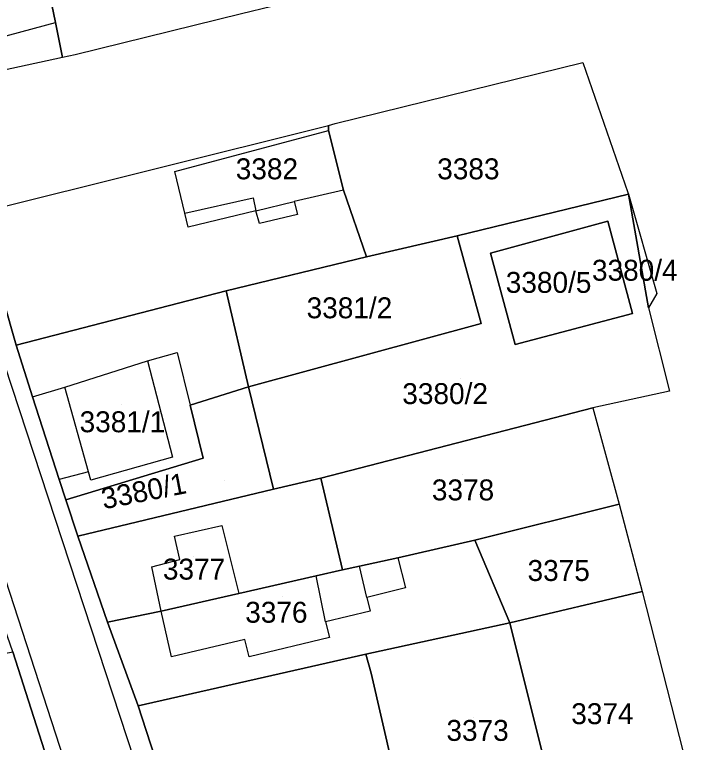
# Model space of a CAD drawing. Extents: x -262657 to -261595, y -1238015 to -1237156.
# Drawn here: x -261971.4 to -261907.1, y -1237612 to -1237542.4 of the extents above; entities that cross this region are included whole.
import ezdxf

# ---------------------------------------------------------------- set-up
doc = ezdxf.new("R2010")
doc.units = 0
for name, color, linetype in [('body_kn', 7, 'Continuous'), ('kladpar_druhypozemkov', 7, 'Continuous'), ('kladpar_hranice', 7, 'Continuous'), ('kladpar_parcelnecisla', 7, 'Continuous'), ('kladpar_plochy', 7, 'Continuous'), ('zappar_hrandruhpozemk', 7, 'Continuous')]:
    doc.layers.add(name, color=color, linetype=linetype)

msp = doc.modelspace()

# ---------------------------------------------------------------- linework, layer by layer
at = {"layer": 'body_kn'}
for p, q in [((-261967.44, -1237543.19), (-261967.44, -1237543.19)), ((-261966.77, -1237546.53), (-261966.77, -1237546.53)), ((-261965.58, -1237546.27), (-261965.58, -1237546.27)), ((-261917.09, -1237547.02), (-261917.09, -1237547.02)), ((-261941.38, -1237553.04), (-261941.38, -1237553.04)), ((-261940.74, -1237552.85), (-261940.74, -1237552.85)), ((-261941.37, -1237553.51), (-261941.37, -1237553.51)), ((-261956.05, -1237557.44), (-261956.05, -1237557.44)), ((-261939.95, -1237559.2), (-261939.95, -1237559.2)), ((-261939.95, -1237559.2), (-261939.95, -1237559.2)), ((-261912.79, -1237559.44), (-261912.79, -1237559.44)), ((-261912.73, -1237559.6), (-261912.73, -1237559.6)), ((-261912.73, -1237559.6), (-261912.73, -1237559.6)), ((-261948.58, -1237559.94), (-261948.58, -1237559.94)), ((-261944.65, -1237560.29), (-261944.65, -1237560.29)), ((-261955.09, -1237561.42), (-261955.09, -1237561.42)), ((-261955.09, -1237561.42), (-261955.09, -1237561.42)), ((-261948.33, -1237561.2), (-261948.33, -1237561.2)), ((-261948.33, -1237561.2), (-261948.33, -1237561.2)), ((-261944.35, -1237561.52), (-261944.35, -1237561.52)), ((-261947.97, -1237562.4), (-261947.97, -1237562.4)), ((-261914.68, -1237562.17), (-261914.68, -1237562.17)), ((-261914.68, -1237562.17), (-261914.68, -1237562.17)), ((-261954.79, -1237562.75), (-261954.79, -1237562.75)), ((-261929.09, -1237563.57), (-261929.09, -1237563.57)), ((-261925.89, -1237565.22), (-261925.89, -1237565.22)), ((-261937.76, -1237565.58), (-261937.76, -1237565.58)), ((-261937.76, -1237565.58), (-261937.76, -1237565.58)), ((-261951.16, -1237568.82), (-261951.16, -1237568.82)), ((-261951.16, -1237568.82), (-261951.16, -1237568.82)), ((-261910.02, -1237569.07), (-261910.02, -1237569.07)), ((-261910.8, -1237570.46), (-261910.8, -1237570.46)), ((-261912.35, -1237570.99), (-261912.35, -1237570.99)), ((-261926.78, -1237571.94), (-261926.78, -1237571.94)), ((-261971.2, -1237574.01), (-261971.2, -1237574.01)), ((-261923.56, -1237573.97), (-261923.56, -1237573.97)), ((-261955.83, -1237574.71), (-261955.83, -1237574.71)), ((-261958.65, -1237575.53), (-261958.65, -1237575.53)), ((-261958.65, -1237575.53), (-261958.65, -1237575.53)), ((-261966.56, -1237578.03), (-261966.56, -1237578.03)), ((-261949.03, -1237578.01), (-261949.03, -1237578.01)), ((-261949.03, -1237578.01), (-261949.03, -1237578.01)), ((-261908.81, -1237578.43), (-261908.81, -1237578.43)), ((-261908.81, -1237578.43), (-261908.81, -1237578.43)), ((-261969.66, -1237578.95), (-261969.66, -1237578.95)), ((-261969.66, -1237578.95), (-261969.66, -1237578.95)), ((-261954.59, -1237579.76), (-261954.59, -1237579.76)), ((-261916.14, -1237580.02), (-261916.14, -1237580.02)), ((-261916.14, -1237580.02), (-261916.14, -1237580.02)), ((-261956.27, -1237584.73), (-261956.27, -1237584.73)), ((-261953.35, -1237584.81), (-261953.35, -1237584.81)), ((-261964.3, -1237586.12), (-261964.3, -1237586.12)), ((-261964.3, -1237586.12), (-261964.3, -1237586.12)), ((-261967.09, -1237586.85), (-261967.09, -1237586.85)), ((-261942.11, -1237586.74), (-261942.11, -1237586.74)), ((-261964.07, -1237586.92), (-261964.07, -1237586.92)), ((-261946.64, -1237587.79), (-261946.64, -1237587.79)), ((-261966.47, -1237588.8), (-261966.47, -1237588.8)), ((-261966.47, -1237588.8), (-261966.47, -1237588.8)), ((-261913.62, -1237589.2), (-261913.62, -1237589.2)), ((-261913.62, -1237589.2), (-261913.62, -1237589.2)), ((-261951.55, -1237591.25), (-261951.55, -1237591.25)), ((-261965.31, -1237592.26), (-261965.31, -1237592.26)), ((-261956.09, -1237592.28), (-261956.09, -1237592.28)), ((-261927.41, -1237592.64), (-261927.41, -1237592.64)), ((-261955.58, -1237594.51), (-261955.58, -1237594.51)), ((-261934.74, -1237594.34), (-261934.74, -1237594.34)), ((-261934.74, -1237594.34), (-261934.74, -1237594.34)), ((-261958.24, -1237595.19), (-261958.24, -1237595.19)), ((-261938.4, -1237595.15), (-261938.4, -1237595.15)), ((-261940.03, -1237595.49), (-261940.03, -1237595.49)), ((-261942.56, -1237596.06), (-261942.56, -1237596.06)), ((-261934.02, -1237597.2), (-261934.02, -1237597.2)), ((-261949.95, -1237597.76), (-261949.95, -1237597.76)), ((-261911.42, -1237597.55), (-261911.42, -1237597.55)), ((-261911.42, -1237597.55), (-261911.42, -1237597.55)), ((-261937.71, -1237598.14), (-261937.71, -1237598.14)), ((-261937.71, -1237598.14), (-261937.71, -1237598.14)), ((-261957.35, -1237599.43), (-261957.35, -1237599.43)), ((-261957.35, -1237599.43), (-261957.35, -1237599.43)), ((-261937.4, -1237599.44), (-261937.4, -1237599.44)), ((-261962.47, -1237600.48), (-261962.47, -1237600.48)), ((-261962.47, -1237600.48), (-261962.47, -1237600.48)), ((-261941.66, -1237600.44), (-261941.66, -1237600.44)), ((-261941.66, -1237600.44), (-261941.66, -1237600.44)), ((-261924.04, -1237600.56), (-261924.04, -1237600.56)), ((-261949.37, -1237602.13), (-261949.37, -1237602.13)), ((-261941.29, -1237601.96), (-261941.29, -1237601.96)), ((-261937.81, -1237603.55), (-261937.81, -1237603.55)), ((-261956.38, -1237603.79), (-261956.38, -1237603.79)), ((-261948.96, -1237603.81), (-261948.96, -1237603.81)), ((-261937.29, -1237605.35), (-261937.29, -1237605.35)), ((-261959.54, -1237608.49), (-261959.54, -1237608.49)), ((-261959.54, -1237608.49), (-261959.54, -1237608.49))]:
    msp.add_line(p, q, dxfattribs=at)
at = {"layer": 'kladpar_druhypozemkov'}
for p, q in [((-261946.28, -1237556.15), (-261946.28, -1237556.15)), ((-261927.37, -1237556.51), (-261927.37, -1237556.51)), ((-261911.2, -1237566.31), (-261911.2, -1237566.31)), ((-261918.68, -1237567.43), (-261918.68, -1237567.43)), ((-261938.36, -1237569.68), (-261938.36, -1237569.68)), ((-261928.79, -1237577.2), (-261928.79, -1237577.2)), ((-261961.16, -1237579.7), (-261961.16, -1237579.7)), ((-261928.56, -1237586.42), (-261928.56, -1237586.42)), ((-261951.29, -1237586.95), (-261951.29, -1237586.95)), ((-261954.3, -1237594.19), (-261954.3, -1237594.19)), ((-261919, -1237595.11), (-261919, -1237595.11)), ((-261945.76, -1237598.07), (-261945.76, -1237598.07)), ((-261915.24, -1237608.62), (-261915.24, -1237608.62)), ((-261927.53, -1237609.57), (-261927.53, -1237609.57))]:
    msp.add_line(p, q, dxfattribs=at)
at = {"layer": 'kladpar_hranice'}
for points in [[(-261949.67, -1237542.35), (-261965.58, -1237546.27), (-261966.77, -1237546.53), (-261967.44, -1237543.19), (-261969.24, -1237534.58), (-261969.44, -1237533.48), (-261966.2, -1237532.71), (-261947.06, -1237528.17), (-261946.6, -1237530.01), (-261943.9, -1237540.93), (-261949.67, -1237542.35)], [(-261979.86, -1237549.38), (-261983.11, -1237536.86), (-261975.94, -1237535.09), (-261969.44, -1237533.48), (-261969.24, -1237534.58), (-261967.44, -1237543.19), (-261966.77, -1237546.53), (-261979.86, -1237549.38)], [(-261983.11, -1237536.86), (-261979.86, -1237549.38), (-261974.85, -1237561.39), (-261971.2, -1237574.01), (-261969.66, -1237578.95), (-261967.09, -1237586.85), (-261966.47, -1237588.8), (-261965.31, -1237592.26), (-261962.47, -1237600.48), (-261959.54, -1237608.49), (-261955.63, -1237620.56)], [(-261963.49, -1237628.42), (-261971.52, -1237603.32), (-261974.52, -1237594.83), (-261976.08, -1237589.98), (-261976.61, -1237588.43), (-261980.66, -1237576.41), (-261981.52, -1237573.9), (-261981.87, -1237572.78), (-261984.6, -1237564.52), (-261986.48, -1237558.8), (-261989.09, -1237551.41), (-261989.35, -1237550.17), (-261991.63, -1237542.33)], [(-261937.76, -1237565.58), (-261939.95, -1237559.2), (-261941.37, -1237553.51), (-261941.38, -1237553.04), (-261940.74, -1237552.85), (-261917.09, -1237547.02), (-261912.79, -1237559.44), (-261912.73, -1237559.6), (-261929.09, -1237563.57), (-261937.76, -1237565.58)], [(-261951.16, -1237568.82), (-261971.2, -1237574.01), (-261974.85, -1237561.39), (-261941.38, -1237553.04), (-261941.37, -1237553.51), (-261939.95, -1237559.2), (-261937.76, -1237565.58), (-261951.16, -1237568.82)], [(-261949.03, -1237578.01), (-261926.78, -1237571.94), (-261929.09, -1237563.57), (-261912.73, -1237559.6), (-261910.8, -1237570.46), (-261908.81, -1237578.43)], [(-261912.73, -1237559.6), (-261910.02, -1237569.07), (-261910.8, -1237570.46), (-261912.73, -1237559.6)], [(-261914.68, -1237562.17), (-261912.35, -1237570.99), (-261923.56, -1237573.97), (-261925.89, -1237565.22), (-261914.68, -1237562.17)], [(-261925.89, -1237565.22), (-261923.56, -1237573.97), (-261912.35, -1237570.99), (-261914.68, -1237562.17), (-261925.89, -1237565.22)], [(-261949.03, -1237578.01), (-261951.16, -1237568.82), (-261937.76, -1237565.58), (-261929.09, -1237563.57), (-261926.78, -1237571.94), (-261949.03, -1237578.01)], [(-261966.47, -1237588.8), (-261967.09, -1237586.85), (-261969.66, -1237578.95), (-261971.2, -1237574.01), (-261951.16, -1237568.82), (-261949.03, -1237578.01), (-261954.59, -1237579.76), (-261953.35, -1237584.81), (-261966.47, -1237588.8)], [(-261966.47, -1237588.8), (-261953.35, -1237584.81), (-261954.59, -1237579.76), (-261949.03, -1237578.01), (-261946.64, -1237587.79), (-261965.31, -1237592.26), (-261966.47, -1237588.8)], [(-261908.81, -1237578.43), (-261916.14, -1237580.02), (-261942.11, -1237586.74), (-261946.64, -1237587.79), (-261949.03, -1237578.01)], [(-261916.14, -1237580.02), (-261913.62, -1237589.2), (-261927.41, -1237592.64), (-261934.74, -1237594.34), (-261938.4, -1237595.15), (-261940.03, -1237595.49), (-261942.11, -1237586.74), (-261916.14, -1237580.02)], [(-261962.47, -1237600.48), (-261965.31, -1237592.26), (-261946.64, -1237587.79), (-261942.11, -1237586.74), (-261940.03, -1237595.49), (-261942.56, -1237596.06), (-261949.95, -1237597.76), (-261957.35, -1237599.43), (-261962.47, -1237600.48)], [(-261913.62, -1237589.2), (-261911.42, -1237597.55), (-261924.04, -1237600.56), (-261927.41, -1237592.64), (-261913.62, -1237589.2)], [(-261959.54, -1237608.49), (-261962.47, -1237600.48), (-261957.35, -1237599.43), (-261949.95, -1237597.76), (-261942.56, -1237596.06), (-261940.03, -1237595.49), (-261938.4, -1237595.15), (-261934.74, -1237594.34), (-261927.41, -1237592.64), (-261924.04, -1237600.56), (-261937.81, -1237603.55), (-261959.54, -1237608.49)], [(-261911.42, -1237597.55), (-261907.09, -1237614.52), (-261919.87, -1237617.28), (-261924.04, -1237600.56), (-261911.42, -1237597.55)], [(-261954.11, -1237624.97), (-261955.63, -1237620.56), (-261934.85, -1237615.92), (-261935.27, -1237614.2), (-261937.29, -1237605.35), (-261937.81, -1237603.55), (-261924.04, -1237600.56), (-261919.87, -1237617.28), (-261922.93, -1237617.93), (-261933.84, -1237620.33), (-261936.24, -1237620.88), (-261949.11, -1237623.82), (-261954.11, -1237624.97)], [(-261971.52, -1237603.32), (-261963.49, -1237628.42), (-261973.11, -1237629.45), (-261987.81, -1237630.03), (-261988.77, -1237624.81), (-261990.82, -1237625.19), (-261994.15, -1237607.67), (-261971.52, -1237603.32)], [(-261955.63, -1237620.56), (-261959.54, -1237608.49), (-261937.81, -1237603.55), (-261937.29, -1237605.35), (-261935.27, -1237614.2), (-261934.85, -1237615.92), (-261955.63, -1237620.56)]]:
    msp.add_lwpolyline(points, dxfattribs=at)
at = {"layer": 'kladpar_plochy'}
for p, q in [((-261929.09, -1237563.57), (-261912.73, -1237559.6)), ((-261912.73, -1237559.6), (-261910.8, -1237570.46)), ((-261914.68, -1237562.17), (-261925.89, -1237565.22)), ((-261912.35, -1237570.99), (-261914.68, -1237562.17)), ((-261926.78, -1237571.94), (-261929.09, -1237563.57)), ((-261925.89, -1237565.22), (-261923.56, -1237573.97)), ((-261910.8, -1237570.46), (-261908.81, -1237578.43)), ((-261923.56, -1237573.97), (-261912.35, -1237570.99)), ((-261949.03, -1237578.01), (-261926.78, -1237571.94)), ((-261946.64, -1237587.79), (-261949.03, -1237578.01)), ((-261908.81, -1237578.43), (-261916.14, -1237580.02)), ((-261916.14, -1237580.02), (-261942.11, -1237586.74)), ((-261942.11, -1237586.74), (-261946.64, -1237587.79))]:
    msp.add_line(p, q, dxfattribs=at)
for points in [[(-261949.67, -1237542.35), (-261965.58, -1237546.27), (-261966.77, -1237546.53), (-261967.44, -1237543.19), (-261969.24, -1237534.58), (-261969.44, -1237533.48), (-261966.2, -1237532.71), (-261947.06, -1237528.17), (-261946.6, -1237530.01), (-261943.9, -1237540.93)], [(-261979.86, -1237549.38), (-261983.11, -1237536.86), (-261975.94, -1237535.09), (-261969.44, -1237533.48), (-261969.24, -1237534.58), (-261967.44, -1237543.19), (-261966.77, -1237546.53)], [(-261937.76, -1237565.58), (-261939.95, -1237559.2), (-261941.37, -1237553.51), (-261941.38, -1237553.04), (-261940.74, -1237552.85), (-261917.09, -1237547.02), (-261912.79, -1237559.44), (-261912.73, -1237559.6), (-261929.09, -1237563.57)], [(-261951.16, -1237568.82), (-261971.2, -1237574.01), (-261974.85, -1237561.39), (-261941.38, -1237553.04), (-261941.37, -1237553.51), (-261939.95, -1237559.2), (-261937.76, -1237565.58)], [(-261912.73, -1237559.6), (-261910.02, -1237569.07), (-261910.8, -1237570.46)], [(-261914.68, -1237562.17), (-261912.35, -1237570.99), (-261923.56, -1237573.97), (-261925.89, -1237565.22)], [(-261949.03, -1237578.01), (-261951.16, -1237568.82), (-261937.76, -1237565.58), (-261929.09, -1237563.57), (-261926.78, -1237571.94)], [(-261966.47, -1237588.8), (-261967.09, -1237586.85), (-261969.66, -1237578.95), (-261971.2, -1237574.01), (-261951.16, -1237568.82), (-261949.03, -1237578.01), (-261954.59, -1237579.76), (-261953.35, -1237584.81)], [(-261966.47, -1237588.8), (-261953.35, -1237584.81), (-261954.59, -1237579.76), (-261949.03, -1237578.01), (-261946.64, -1237587.79), (-261965.31, -1237592.26)], [(-261916.14, -1237580.02), (-261913.62, -1237589.2), (-261927.41, -1237592.64), (-261934.74, -1237594.34), (-261938.4, -1237595.15), (-261940.03, -1237595.49), (-261942.11, -1237586.74)], [(-261962.47, -1237600.48), (-261965.31, -1237592.26), (-261946.64, -1237587.79), (-261942.11, -1237586.74), (-261940.03, -1237595.49), (-261942.56, -1237596.06), (-261949.95, -1237597.76), (-261957.35, -1237599.43)], [(-261913.62, -1237589.2), (-261911.42, -1237597.55), (-261924.04, -1237600.56), (-261927.41, -1237592.64)], [(-261959.54, -1237608.49), (-261962.47, -1237600.48), (-261957.35, -1237599.43), (-261949.95, -1237597.76), (-261942.56, -1237596.06), (-261940.03, -1237595.49), (-261938.4, -1237595.15), (-261934.74, -1237594.34), (-261927.41, -1237592.64), (-261924.04, -1237600.56), (-261937.81, -1237603.55)], [(-261911.42, -1237597.55), (-261907.09, -1237614.52), (-261919.87, -1237617.28), (-261924.04, -1237600.56)], [(-261954.11, -1237624.97), (-261955.63, -1237620.56), (-261934.85, -1237615.92), (-261935.27, -1237614.2), (-261937.29, -1237605.35), (-261937.81, -1237603.55), (-261924.04, -1237600.56), (-261919.87, -1237617.28), (-261922.93, -1237617.93), (-261933.84, -1237620.33), (-261936.24, -1237620.88), (-261949.11, -1237623.82)], [(-261971.52, -1237603.32), (-261963.49, -1237628.42), (-261973.11, -1237629.45), (-261987.81, -1237630.03), (-261988.77, -1237624.81), (-261990.82, -1237625.19), (-261994.15, -1237607.67)], [(-261955.63, -1237620.56), (-261959.54, -1237608.49), (-261937.81, -1237603.55), (-261937.29, -1237605.35), (-261935.27, -1237614.2), (-261934.85, -1237615.92)]]:
    msp.add_lwpolyline(points, close=True, dxfattribs=at)
for points in [[(-261983.11, -1237536.86), (-261979.86, -1237549.38), (-261974.85, -1237561.39), (-261971.2, -1237574.01), (-261969.66, -1237578.95), (-261967.09, -1237586.85), (-261966.47, -1237588.8), (-261965.31, -1237592.26), (-261962.47, -1237600.48), (-261959.54, -1237608.49), (-261955.63, -1237620.56)], [(-261963.49, -1237628.42), (-261971.52, -1237603.32), (-261974.52, -1237594.83), (-261976.08, -1237589.98), (-261976.61, -1237588.43), (-261980.66, -1237576.41), (-261981.52, -1237573.9), (-261981.87, -1237572.78), (-261984.6, -1237564.52), (-261986.48, -1237558.8), (-261989.09, -1237551.41), (-261989.35, -1237550.17), (-261991.63, -1237542.33)]]:
    msp.add_lwpolyline(points, dxfattribs=at)
at = {"layer": 'zappar_hrandruhpozemk'}
for p, q in [((-261976.12, -1237545.5), (-261967.44, -1237543.19)), ((-261956.05, -1237557.44), (-261941.37, -1237553.51)), ((-261955.09, -1237561.42), (-261948.58, -1237559.94)), ((-261948.58, -1237559.94), (-261948.33, -1237561.2)), ((-261948.33, -1237561.2), (-261944.65, -1237560.29)), ((-261944.35, -1237561.52), (-261947.97, -1237562.4)), ((-261976.86, -1237562.12), (-261952.08, -1237637.52)), ((-261955.83, -1237574.71), (-261954.59, -1237579.76)), ((-261957.8, -1237640.72), (-261978.89, -1237575.95)), ((-261964.3, -1237586.12), (-261966.56, -1237578.03)), ((-261956.09, -1237592.28), (-261951.55, -1237591.25)), ((-261951.55, -1237591.25), (-261949.95, -1237597.76)), ((-261937.71, -1237598.14), (-261938.4, -1237595.15)), ((-261941.66, -1237600.44), (-261942.56, -1237596.06)), ((-261941.29, -1237601.96), (-261948.96, -1237603.81))]:
    msp.add_line(p, q, dxfattribs=at)
for points in [[(-261947.97, -1237562.4), (-261948.33, -1237561.2), (-261954.79, -1237562.75), (-261955.09, -1237561.42), (-261956.05, -1237557.44)], [(-261939.95, -1237559.2), (-261944.65, -1237560.29), (-261944.35, -1237561.52)], [(-261969.66, -1237578.95), (-261966.56, -1237578.03), (-261958.65, -1237575.53), (-261955.83, -1237574.71)], [(-261958.65, -1237575.53), (-261956.27, -1237584.73), (-261964.07, -1237586.92), (-261964.3, -1237586.12), (-261967.09, -1237586.85)], [(-261957.35, -1237599.43), (-261958.24, -1237595.19), (-261955.58, -1237594.51), (-261956.09, -1237592.28)], [(-261934.74, -1237594.34), (-261934.02, -1237597.2), (-261937.71, -1237598.14), (-261937.4, -1237599.44), (-261941.66, -1237600.44), (-261941.29, -1237601.96)], [(-261948.96, -1237603.81), (-261949.37, -1237602.13), (-261956.38, -1237603.79), (-261957.35, -1237599.43)]]:
    msp.add_lwpolyline(points, dxfattribs=at)

# ---------------------------------------------------------------- texts
at = {"layer": 'kladpar_parcelnecisla'}
for s, p in [('3382', (-261950.233, -1237558.17)), ('3383', (-261930.989, -1237558.17)), ('3380/4', (-261916.208, -1237567.86)), ('3380/5', (-261924.443, -1237569.02)), ('3381/2', (-261943.463, -1237571.45)), ('3380/2', (-261934.324, -1237579.65)), ('3381/1', (-261965.147, -1237582.34)), ('3378', (-261931.501, -1237588.85)), ('3377', (-261957.19, -1237596.42)), ('3375', (-261922.363, -1237596.55)), ('3376', (-261949.327, -1237600.54)), ('3374', (-261918.187, -1237610.23)), ('3373', (-261930.11, -1237611.83))]:
    msp.add_text(s, height=2, dxfattribs=at).set_placement(p)
msp.add_text('3380/1', height=2, rotation=11, dxfattribs=at).set_placement((-261962.851, -1237589.71))

doc.saveas('drawing.dxf')
